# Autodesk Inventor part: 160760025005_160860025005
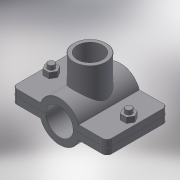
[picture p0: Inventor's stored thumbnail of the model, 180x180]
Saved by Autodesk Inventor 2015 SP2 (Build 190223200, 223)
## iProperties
Created: 2017-05
Part Number: 160760025005_160860025005
Material: Generic
Description: PLASSON SADDLE 25-1/2"
Document SubType Name: Modeling
Designer: KIM
Density: 1 g/cm^3
Appearance: Default
Author: KIM
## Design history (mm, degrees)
derived "16076.ipt"
feature "Solid1::16076.ipt"
feature "Solid2::16076.ipt"
tag "TaggingFeature1"
body "Solid1"
other parameters: "d0" = 37.5, "d1" = 75, "d2" = 12.5, "d3" = 25, "d5" = 0, "d6" = 3.75, "d7" = 75, "d8" = 0.1, "d10" = 0, "d11" = 0.25, "d14" = 24.2203, "d20" = 0.25, "d23" = 0.25, "d36" = 8, "d37" = 6.4, "d38" = 20.5, "d39" = 0, "d40" = 3, "d41" = 4, "d42" = 0, "d43" = 5, "d44" = 3, "d45" = 0, "d46" = 0.25, "d51" = 36, "d52" = 18.631, "d53" = 18, "d54" = 0, "d55" = 15, "d57" = 0, "d58" = 27, "d60" = 0, "d62" = 8, "d63" = 25, "d66" = 0, "d_" = 25, "B_" = 15, "G_" = 18.631, "A_" = 36, "L_" = 75, "l_2" = 18
